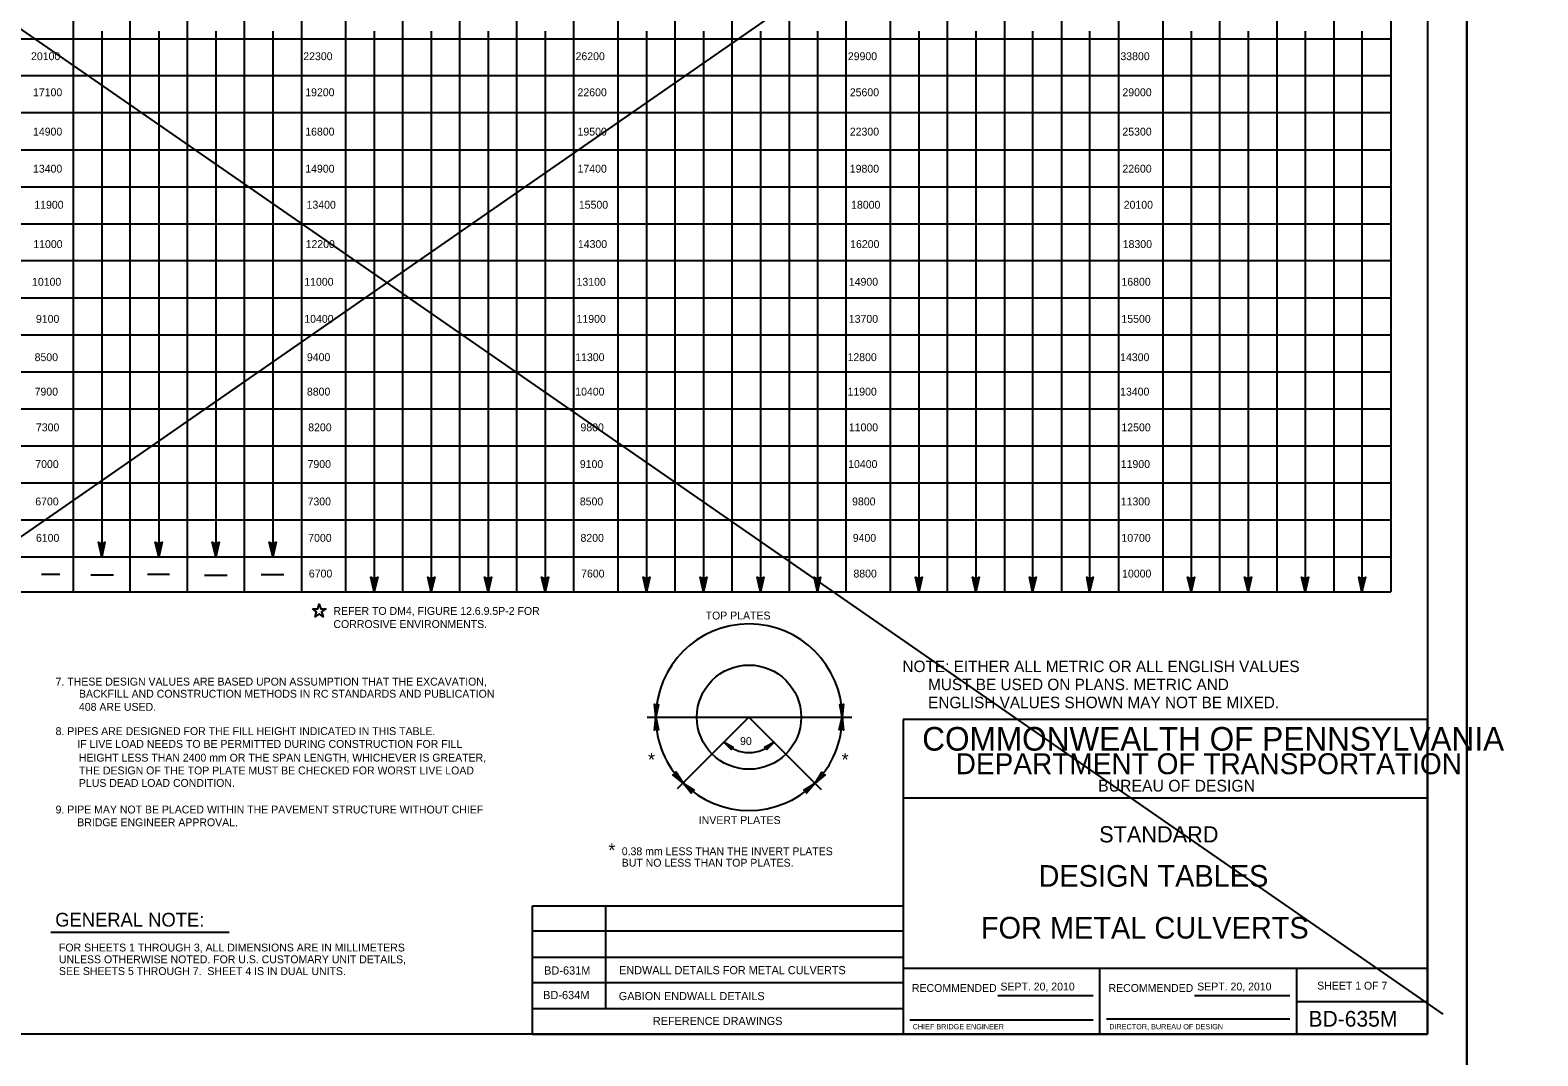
# Model space of a CAD drawing. Extents: x 591 to 2288, y -189 to 2187.
# Drawn here: x 884 to 1459, y 1600 to 1991 of the extents above; entities that cross this region are included whole.
import ezdxf

# ---------------------------------------------------------------- set-up
doc = ezdxf.new("R2010")
doc.units = 0
for name, color, linetype in [('1', 7, 'Continuous'), ('2', 7, 'Continuous'), ('PLT-BNDY', 7, 'Continuous')]:
    doc.layers.add(name, color=color, linetype=linetype)

msp = doc.modelspace()

# ---------------------------------------------------------------- linework, layer by layer
at = {"layer": '1'}
for p, q in [((1418.7, 2171.02), (604.95, 1606.73)), ((627.68, 2166.47), (1423.24, 1615.83)), ((1292.34, 1608.21), (1292.34, 1633.21)), ((1367.34, 1633.21), (1367.34, 1608.21)), ((1253.43, 1622.93), (1289.84, 1622.93)), ((1328.43, 1622.93), (1364.84, 1622.93)), ((1219.84, 1613.71), (1289.84, 1613.71)), ((1294.84, 1614.09), (1364.84, 1614.09))]:
    msp.add_line(p, q, dxfattribs=at)
at = {"layer": '2'}
for p, q in [((1417.34, 2172.21), (1417.34, 1608.21)), ((987.71, 2055.84), (987.71, 1776.84)), ((1091.59, 2055.84), (1091.59, 1776.84)), ((1195.46, 2055.84), (1195.46, 1776.84)), ((1299.46, 2055.84), (1299.46, 1776.84)), ((1403.34, 2055.84), (1403.34, 1776.84)), ((900.71, 2044.21), (900.71, 1776.84)), ((1004.59, 2044.21), (1004.59, 1776.84)), ((1108.46, 2044.21), (1108.46, 1776.84)), ((1212.34, 2044.21), (1212.34, 1776.84)), ((1316.34, 2044.21), (1316.34, 1776.84)), ((944.09, 2034.21), (944.09, 1776.84)), ((1048.09, 2034.21), (1048.09, 1776.84)), ((1151.96, 2034.21), (1151.96, 1776.84)), ((1255.96, 2034.21), (1255.96, 1776.84)), ((1359.84, 2034.21), (1359.84, 1776.84)), ((922.34, 2020.21), (922.34, 1776.84)), ((965.84, 2020.21), (965.84, 1776.84)), ((1026.34, 2020.21), (1026.34, 1776.84)), ((1069.84, 2020.21), (1069.84, 1776.84)), ((1130.21, 2020.21), (1130.21, 1776.84)), ((1173.84, 2020.21), (1173.84, 1776.84)), ((1234.09, 2020.21), (1234.09, 1776.84)), ((1277.71, 2020.21), (1277.71, 1776.84)), ((1337.96, 2020.21), (1337.96, 1776.84)), ((1381.59, 2020.21), (1381.59, 1776.84)), ((911.59, 1990.59), (911.59, 1790.21)), ((933.34, 1990.59), (933.34, 1790.21)), ((955.09, 1990.59), (955.09, 1790.21)), ((976.84, 1990.59), (976.84, 1790.21)), ((1015.46, 1990.59), (1015.46, 1776.84)), ((1037.21, 1990.59), (1037.21, 1776.84)), ((1058.96, 1990.59), (1058.96, 1776.84)), ((1080.71, 1990.59), (1080.71, 1776.84)), ((1119.34, 1990.59), (1119.34, 1776.84)), ((1141.09, 1990.59), (1141.09, 1776.84)), ((1162.84, 1990.59), (1162.84, 1776.84)), ((1184.59, 1990.59), (1184.59, 1776.84)), ((1223.34, 1990.59), (1223.34, 1776.84)), ((1245.09, 1990.59), (1245.09, 1776.84)), ((1266.71, 1990.59), (1266.71, 1776.84)), ((1288.46, 1990.59), (1288.46, 1776.84)), ((1327.21, 1990.59), (1327.21, 1776.84)), ((1348.96, 1990.59), (1348.96, 1776.84)), ((1370.71, 1990.59), (1370.71, 1776.84)), ((1392.34, 1990.59), (1392.34, 1776.84)), ((651.34, 1987.71), (1403.34, 1987.71)), ((651.34, 1973.71), (1403.34, 1973.71)), ((651.34, 1959.59), (1403.34, 1959.59)), ((651.34, 1945.46), (1403.34, 1945.46)), ((651.34, 1931.34), (1403.34, 1931.34)), ((651.34, 1917.21), (1403.34, 1917.21)), ((651.34, 1903.21), (1403.34, 1903.21)), ((651.34, 1888.96), (1403.34, 1888.96)), ((651.34, 1874.84), (1403.34, 1874.84)), ((651.34, 1860.71), (1403.34, 1860.71)), ((651.34, 1846.59), (1403.34, 1846.59)), ((651.34, 1832.59), (1403.34, 1832.59)), ((651.34, 1818.46), (1403.34, 1818.46)), ((651.34, 1804.34), (1403.34, 1804.34)), ((651.34, 1790.21), (1403.34, 1790.21)), ((888.59, 1783.59), (895.59, 1783.59)), ((907.46, 1783.34), (916.09, 1783.34)), ((928.96, 1783.59), (937.46, 1783.59)), ((950.71, 1783.21), (959.46, 1783.21)), ((972.34, 1783.46), (981.09, 1783.46)), ((651.34, 1776.84), (1403.34, 1776.84)), ((994.46, 1769.46), (994.46, 1769.46)), ((1119.59, 1729.09), (1197.71, 1729.09)), ((1158.46, 1729.09), (1131.09, 1701.71)), ((1158.46, 1729.09), (1186.09, 1701.46)), ((1417.34, 1728.21), (1217.34, 1728.21)), ((1217.34, 1728.21), (1217.34, 1608.21)), ((1417.34, 1608.21), (1417.34, 1728.21)), ((1417.34, 1698.21), (1217.34, 1698.21)), ((1075.96, 1608.21), (1075.96, 1657.21)), ((1075.96, 1657.21), (1217.34, 1657.21)), ((1075.96, 1657.21), (1217.34, 1657.21)), ((1103.84, 1618.34), (1103.84, 1657.21)), ((892.16, 1647.09), (960.23, 1647.09)), ((1075.96, 1647.59), (1217.34, 1647.59)), ((1075.96, 1637.59), (1217.34, 1637.59)), ((1075.96, 1627.96), (1217.34, 1627.96)), ((1417.34, 1633.21), (1217.34, 1633.21)), ((1075.96, 1617.96), (1217.34, 1617.96)), ((1367.34, 1620.71), (1417.34, 1620.71)), ((1417.34, 1608.21), (631.34, 1608.21)), ((1075.96, 1608.21), (1217.34, 1608.21)), ((1217.34, 1608.21), (1417.34, 1608.21))]:
    msp.add_line(p, q, dxfattribs=at)
for points in [[(912.59, 1795.59), (911.96, 1795.34), (911.59, 1790.21), (912.59, 1795.59), (912.71, 1795.84), (911.59, 1790.21), (911.09, 1795.34), (910.59, 1795.59), (911.59, 1790.21), (910.34, 1795.84), (910.59, 1795.59)], [(934.21, 1795.59), (933.71, 1795.34), (933.34, 1790.21), (934.21, 1795.59), (934.59, 1795.84), (933.34, 1790.21), (932.96, 1795.34), (932.34, 1795.59), (933.34, 1790.21), (931.96, 1795.84), (932.34, 1795.59)], [(955.96, 1795.59), (955.34, 1795.34), (955.09, 1790.21), (955.96, 1795.59), (956.34, 1795.84), (955.09, 1790.21), (954.71, 1795.34), (954.09, 1795.59), (955.09, 1790.21), (953.71, 1795.84), (954.09, 1795.59)], [(977.71, 1795.59), (977.09, 1795.34), (976.84, 1790.21), (977.71, 1795.59), (978.09, 1795.84), (976.84, 1790.21), (976.46, 1795.34), (975.84, 1795.59), (976.84, 1790.21), (975.46, 1795.84), (975.84, 1795.59)], [(1016.46, 1782.21), (1015.84, 1782.09), (1015.46, 1776.84), (1016.46, 1782.21), (1016.84, 1782.46), (1015.46, 1776.84), (1015.09, 1781.96), (1014.59, 1782.21), (1015.46, 1776.84), (1014.21, 1782.46), (1014.59, 1782.21)], [(1038.21, 1782.21), (1037.59, 1782.09), (1037.21, 1776.84), (1038.21, 1782.21), (1038.59, 1782.46), (1037.21, 1776.84), (1036.84, 1781.96), (1036.21, 1782.21), (1037.21, 1776.84), (1035.96, 1782.46), (1036.21, 1782.21)], [(1059.84, 1782.21), (1059.34, 1782.09), (1058.96, 1776.84), (1059.84, 1782.21), (1060.21, 1782.46), (1058.96, 1776.84), (1058.59, 1781.96), (1057.96, 1782.21), (1058.96, 1776.84), (1057.59, 1782.46), (1057.96, 1782.21)], [(1081.59, 1782.21), (1081.21, 1782.09), (1080.71, 1776.84), (1081.59, 1782.21), (1081.96, 1782.46), (1080.71, 1776.84), (1080.34, 1781.96), (1079.71, 1782.21), (1080.71, 1776.84), (1079.34, 1782.46), (1079.71, 1782.21)], [(1120.34, 1782.21), (1119.71, 1782.09), (1119.34, 1776.84), (1120.34, 1782.21), (1120.71, 1782.46), (1119.34, 1776.84), (1119.09, 1781.96), (1118.46, 1782.21), (1119.34, 1776.84), (1118.09, 1782.46), (1118.46, 1782.21)], [(1142.09, 1782.21), (1141.46, 1782.09), (1141.09, 1776.84), (1142.09, 1782.21), (1142.46, 1782.46), (1141.09, 1776.84), (1140.71, 1781.96), (1140.21, 1782.21), (1141.09, 1776.84), (1139.84, 1782.46), (1140.21, 1782.21)], [(1163.84, 1782.21), (1163.21, 1782.09), (1162.84, 1776.84), (1163.84, 1782.21), (1164.21, 1782.46), (1162.84, 1776.84), (1162.46, 1781.96), (1161.96, 1782.21), (1162.84, 1776.84), (1161.59, 1782.46), (1161.96, 1782.21)], [(1185.59, 1782.21), (1185.09, 1782.09), (1184.59, 1776.84), (1185.59, 1782.21), (1185.84, 1782.46), (1184.59, 1776.84), (1184.21, 1781.96), (1183.59, 1782.21), (1184.59, 1776.84), (1183.34, 1782.46), (1183.59, 1782.21)], [(1224.21, 1782.21), (1223.71, 1782.09), (1223.34, 1776.84), (1224.21, 1782.21), (1224.59, 1782.46), (1223.34, 1776.84), (1222.96, 1781.96), (1222.34, 1782.21), (1223.34, 1776.84), (1221.96, 1782.46), (1222.34, 1782.21)], [(1245.96, 1782.21), (1245.34, 1782.09), (1245.09, 1776.84), (1245.96, 1782.21), (1246.34, 1782.46), (1245.09, 1776.84), (1244.71, 1781.96), (1244.09, 1782.21), (1245.09, 1776.84), (1243.71, 1782.46), (1244.09, 1782.21)], [(1267.71, 1782.21), (1267.21, 1782.09), (1266.71, 1776.84), (1267.71, 1782.21), (1268.09, 1782.46), (1266.71, 1776.84), (1266.46, 1781.96), (1265.84, 1782.21), (1266.71, 1776.84), (1265.46, 1782.46), (1265.84, 1782.21)], [(1289.46, 1782.21), (1288.96, 1782.09), (1288.46, 1776.84), (1289.46, 1782.21), (1289.84, 1782.46), (1288.46, 1776.84), (1288.09, 1781.96), (1287.71, 1782.21), (1288.46, 1776.84), (1287.34, 1782.46), (1287.71, 1782.21)], [(1328.21, 1782.21), (1327.59, 1782.09), (1327.21, 1776.84), (1328.21, 1782.21), (1328.46, 1782.46), (1327.21, 1776.84), (1326.84, 1781.96), (1326.21, 1782.21), (1327.21, 1776.84), (1325.84, 1782.46), (1326.21, 1782.21)], [(1349.84, 1782.21), (1349.46, 1782.09), (1348.96, 1776.84), (1349.84, 1782.21), (1350.21, 1782.46), (1348.96, 1776.84), (1348.59, 1781.96), (1347.96, 1782.21), (1348.96, 1776.84), (1347.59, 1782.46), (1347.96, 1782.21)], [(1371.59, 1782.21), (1371.09, 1782.09), (1370.71, 1776.84), (1371.59, 1782.21), (1371.96, 1782.46), (1370.71, 1776.84), (1370.34, 1781.96), (1369.84, 1782.21), (1370.71, 1776.84), (1369.34, 1782.46), (1369.84, 1782.21)], [(1393.46, 1782.21), (1392.84, 1782.09), (1392.34, 1776.84), (1393.46, 1782.21), (1393.71, 1782.46), (1392.34, 1776.84), (1392.09, 1781.96), (1391.59, 1782.21), (1392.34, 1776.84), (1391.21, 1782.46), (1391.59, 1782.21)], [(991.96, 1770.34), (993.96, 1770.34), (994.46, 1772.21), (995.09, 1770.34), (997.09, 1770.34), (995.46, 1769.21), (996.09, 1767.34), (994.46, 1768.46), (992.96, 1767.34), (993.46, 1769.21), (991.96, 1770.34)], [(1123.84, 1733.71), (1123.46, 1733.59), (1122.96, 1729.09), (1123.84, 1733.71), (1123.96, 1733.96), (1122.96, 1729.09), (1122.96, 1733.59), (1122.59, 1733.84), (1122.96, 1729.09), (1122.46, 1734.09), (1122.59, 1733.84)], [(1194.46, 1733.84), (1194.09, 1733.59), (1194.09, 1729.09), (1194.46, 1733.84), (1194.59, 1734.09), (1194.09, 1729.09), (1193.59, 1733.59), (1193.21, 1733.71), (1194.09, 1729.09), (1193.09, 1733.96), (1193.21, 1733.71)], [(1122.59, 1724.34), (1122.96, 1724.59), (1122.96, 1729.09), (1122.59, 1724.34), (1122.46, 1724.09), (1122.96, 1729.09), (1123.46, 1724.59), (1123.71, 1724.46), (1122.96, 1729.09), (1123.96, 1724.21), (1123.71, 1724.46)], [(1193.21, 1724.46), (1193.59, 1724.59), (1194.09, 1729.09), (1193.21, 1724.46), (1192.96, 1724.21), (1194.09, 1729.09), (1194.09, 1724.59), (1194.34, 1724.34), (1194.09, 1729.09), (1194.59, 1724.09), (1194.34, 1724.34)], [(1151.71, 1716.96), (1151.71, 1717.21), (1148.96, 1719.59), (1151.71, 1716.96), (1151.71, 1716.71), (1148.96, 1719.59), (1151.96, 1717.59), (1152.21, 1717.71), (1148.96, 1719.59), (1152.46, 1717.71), (1152.21, 1717.71)], [(1164.71, 1717.71), (1165.09, 1717.59), (1168.09, 1719.59), (1164.71, 1717.71), (1164.46, 1717.71), (1168.09, 1719.59), (1165.21, 1717.21), (1165.34, 1716.96), (1168.09, 1719.59), (1165.34, 1716.71), (1165.34, 1716.96)], [(1130.59, 1707.84), (1130.46, 1707.46), (1133.34, 1703.96), (1130.59, 1707.84), (1130.59, 1708.21), (1133.34, 1703.96), (1130.21, 1707.21), (1129.84, 1707.09), (1133.34, 1703.96), (1129.46, 1707.09), (1129.84, 1707.09)], [(1136.46, 1700.34), (1136.59, 1700.71), (1133.34, 1703.96), (1136.46, 1700.34), (1136.46, 1700.09), (1133.34, 1703.96), (1136.84, 1701.09), (1137.21, 1701.21), (1133.34, 1703.96), (1137.59, 1701.21), (1137.21, 1701.21)], [(1179.71, 1701.21), (1180.09, 1701.09), (1183.71, 1703.96), (1179.71, 1701.21), (1179.46, 1701.21), (1183.71, 1703.96), (1180.46, 1700.71), (1180.59, 1700.34), (1183.71, 1703.96), (1180.46, 1700.09), (1180.59, 1700.34)], [(1187.21, 1707.09), (1186.84, 1707.09), (1183.71, 1703.96), (1187.21, 1707.09), (1187.59, 1707.09), (1183.71, 1703.96), (1186.46, 1707.46), (1186.34, 1707.84), (1183.71, 1703.96), (1186.34, 1708.09), (1186.34, 1707.84)]]:
    msp.add_lwpolyline(points, dxfattribs=at)
msp.add_circle((1158.51, 1729.09), 19.88, dxfattribs=at)
for radius, start, end in [(35.56, 0.01323, 179.98674), (35.56, 180, 225.00216), (35.56, 315, 0), (13.49, 225.00216, 315), (35.56, 225.00216, 315)]:
    msp.add_arc((1158.51, 1729.09), radius, start, end, dxfattribs=at)
at = {"layer": 'PLT-BNDY'}
for points in [[(591.34, 2187.21), (1432.34, 2187.21), (1432.34, 1593.21), (591.34, 1593.21)], [(1432.34, 2187.21), (2273.34, 2187.21), (2273.34, 1593.21), (1432.34, 1593.21)]]:
    msp.add_lwpolyline(points, close=True, dxfattribs=at)

# ---------------------------------------------------------------- texts
at = {"layer": '1'}
for s, height, p in [('RECOMMENDED', 3, (1220.67, 1624.34)), ('RECOMMENDED', 3, (1295.67, 1624.34)), ('CHIEF BRIDGE ENGINEER', 2.0003, (1220.93, 1610.09)), ('DIRECTOR, BUREAU OF DESIGN', 2.0003, (1295.94, 1610.09))]:
    msp.add_text(s, height=height, dxfattribs=at).set_placement(p)
at = {"layer": '2'}
for s, height, p in [('20100', 3, (884.59, 1979.59)), ('22300', 3, (988.46, 1979.59)), ('26200', 3, (1092.34, 1979.59)), ('29900', 3, (1196.21, 1979.59)), ('33800', 3, (1300.21, 1979.59)), ('17100', 3, (885.34, 1965.84)), ('19200', 3, (989.21, 1965.84)), ('22600', 3, (1093.09, 1965.84)), ('25600', 3, (1196.96, 1965.84)), ('29000', 3, (1300.96, 1965.84)), ('14900', 3, (885.34, 1950.84)), ('16800', 3, (989.21, 1950.84)), ('19500', 3, (1093.09, 1950.84)), ('22300', 3, (1196.96, 1950.84)), ('25300', 3, (1300.96, 1950.84)), ('13400', 3, (885.34, 1936.71)), ('14900', 3, (989.21, 1936.71)), ('17400', 3, (1093.09, 1936.71)), ('19800', 3, (1196.96, 1936.71)), ('22600', 3, (1300.96, 1936.71)), ('11900', 3, (885.84, 1922.96)), ('13400', 3, (989.71, 1922.96)), ('15500', 3, (1093.59, 1922.96)), ('18000', 3, (1197.46, 1922.96)), ('20100', 3, (1301.46, 1922.96)), ('11000', 3, (885.46, 1907.96)), ('12200', 3, (989.34, 1907.96)), ('14300', 3, (1093.21, 1907.96)), ('16200', 3, (1197.09, 1907.96)), ('18300', 3, (1301.09, 1907.96)), ('10100', 3, (884.96, 1893.59)), ('11000', 3, (988.84, 1893.59)), ('13100', 3, (1092.71, 1893.59)), ('14900', 3, (1196.59, 1893.59)), ('16800', 3, (1300.59, 1893.59)), ('9100', 3, (886.46, 1879.46)), ('10400', 3, (988.84, 1879.46)), ('11900', 3, (1092.71, 1879.46)), ('13700', 3, (1196.59, 1879.46)), ('15500', 3, (1300.59, 1879.46)), ('8500', 3, (885.96, 1864.84)), ('9400', 3, (989.84, 1864.84)), ('11300', 3, (1092.21, 1864.84)), ('12800', 3, (1196.09, 1864.84)), ('14300', 3, (1300.09, 1864.84)), ('7900', 3, (885.96, 1851.71)), ('8800', 3, (989.84, 1851.71)), ('10400', 3, (1092.21, 1851.71)), ('11900', 3, (1196.09, 1851.71)), ('13400', 3, (1300.09, 1851.71)), ('7300', 3, (886.46, 1838.09)), ('8200', 3, (990.34, 1838.09)), ('9800', 3, (1094.21, 1838.09)), ('11000', 3, (1196.59, 1838.09)), ('12500', 3, (1300.59, 1838.09)), ('7000', 3, (886.21, 1824.09)), ('7900', 3, (990.09, 1824.09)), ('9100', 3, (1093.96, 1824.09)), ('10400', 3, (1196.34, 1824.09)), ('11900', 3, (1300.34, 1824.09)), ('6700', 3, (886.21, 1809.84)), ('7300', 3, (990.09, 1809.84)), ('8500', 3, (1093.96, 1809.84)), ('9800', 3, (1197.84, 1809.84)), ('11300', 3, (1300.34, 1809.84)), ('6100', 3, (886.46, 1795.96)), ('7000', 3, (990.34, 1795.96)), ('8200', 3, (1094.21, 1795.96)), ('9400', 3, (1198.09, 1795.96)), ('10700', 3, (1300.59, 1795.96)), ('6700', 3, (990.59, 1782.34)), ('7600', 3, (1094.46, 1782.34)), ('8800', 3, (1198.34, 1782.34)), ('10000', 3, (1300.84, 1782.34)), ('CORROSIVE ENVIRONMENTS.', 3, (999.96, 1763.09)), ('REFER TO DM4, FIGURE 12.6.9.5P-2 FOR', 3, (999.96, 1768.09)), ('TOP PLATES', 3, (1141.96, 1766.34)), ('NOTE: EITHER ALL METRIC OR ALL ENGLISH VALUES', 4.375, (1217.07, 1746.27)), ('7. THESE DESIGN VALUES ARE BASED UPON ASSUMPTION THAT THE EXCAVATION,', 3, (893.96, 1741.15)), ('      MUST BE USED ON PLANS. METRIC AND', 4.375, (1217.07, 1739.39)), ('BACKFILL AND CONSTRUCTION METHODS IN RC STANDARDS AND PUBLICATION', 3, (902.88, 1736.52)), ('408 ARE USED.', 3, (902.86, 1731.52)), ('      ENGLISH VALUES SHOWN MAY NOT BE MIXED.', 4.375, (1217.07, 1732.52)), ('8. PIPES ARE DESIGNED FOR THE FILL HEIGHT INDICATED IN THIS TABLE.', 3, (893.95, 1722.27)), ('IF LIVE LOAD NEEDS TO BE PERMITTED DURING CONSTRUCTION FOR FILL', 3, (902.22, 1717.4)), ('90', 3, (1155.09, 1718.46)), ('COMMONWEALTH OF PENNSYLVANIA', 9, (1224.59, 1716.34)), ('HEIGHT LESS THAN 2400 mm OR THE SPAN LENGTH, WHICHEVER IS GREATER,', 3, (902.84, 1712.15)), ('*', 5.13, (1119.96, 1710.34)), ('*', 5.13, (1193.84, 1710.34)), ('DEPARTMENT OF TRANSPORTATION', 8.0002, (1237.34, 1707.34)), ('THE DESIGN OF THE TOP PLATE MUST BE CHECKED FOR WORST LIVE LOAD', 3, (902.88, 1707.27)), ('PLUS DEAD LOAD CONDITION.', 3, (902.84, 1702.52)), ('BUREAU OF DESIGN', 4.5, (1291.71, 1700.71)), ('9. PIPE MAY NOT BE PLACED WITHIN THE PAVEMENT STRUCTURE WITHOUT CHIEF', 3, (893.95, 1692.38)), ('INVERT PLATES', 3, (1139.34, 1688.34)), ('BRIDGE ENGINEER APPROVAL.', 3, (902.22, 1687.5)), ('STANDARD', 6.188, (1292.09, 1681.34)), ('*', 5.13, (1104.84, 1675.84)), ('0.38 mm LESS THAN THE INVERT PLATES', 3, (1109.96, 1676.46)), ('BUT NO LESS THAN TOP PLATES.', 3, (1109.96, 1672.09)), ('DESIGN TABLES', 8.2515, (1268.96, 1664.44)), ('GENERAL NOTE:', 5.2423, (893.82, 1649.25)), ('FOR METAL CULVERTS', 8.2515, (1246.96, 1644.68)), ('   FOR SHEETS 1 THROUGH 3, ALL DIMENSIONS ARE IN MILLIMETERS', 3, (891.9, 1639.76)), ('   SEE SHEETS 5 THROUGH 7.  SHEET 4 IS IN DUAL UNITS.', 3, (891.9, 1630.76)), ('   UNLESS OTHERWISE NOTED. FOR U.S. CUSTOMARY UNIT DETAILS,', 3, (891.9, 1635.26)), ('BD-631M', 3.125, (1080.34, 1630.96)), ('ENDWALL DETAILS FOR METAL CULVERTS', 3.0938, (1108.96, 1631.09)), ('SEPT. 20, 2010', 3, (1254.43, 1624.89)), ('SHEET 1 OF 7', 3, (1375.28, 1625.23)), ('BD-634M', 3.125, (1079.96, 1621.59)), ('GABION ENDWALL DETAILS', 3.0938, (1108.84, 1621.21)), ('BD-635M', 6, (1371.96, 1611.09)), ('REFERENCE DRAWINGS', 3.093, (1121.84, 1611.71))]:
    msp.add_text(s, height=height, dxfattribs=at).set_placement(p)
msp.add_text('SEPT. 20, 2010', height=3, rotation=360, dxfattribs=at).set_placement((1329.52, 1624.89))

doc.saveas('drawing.dxf')
